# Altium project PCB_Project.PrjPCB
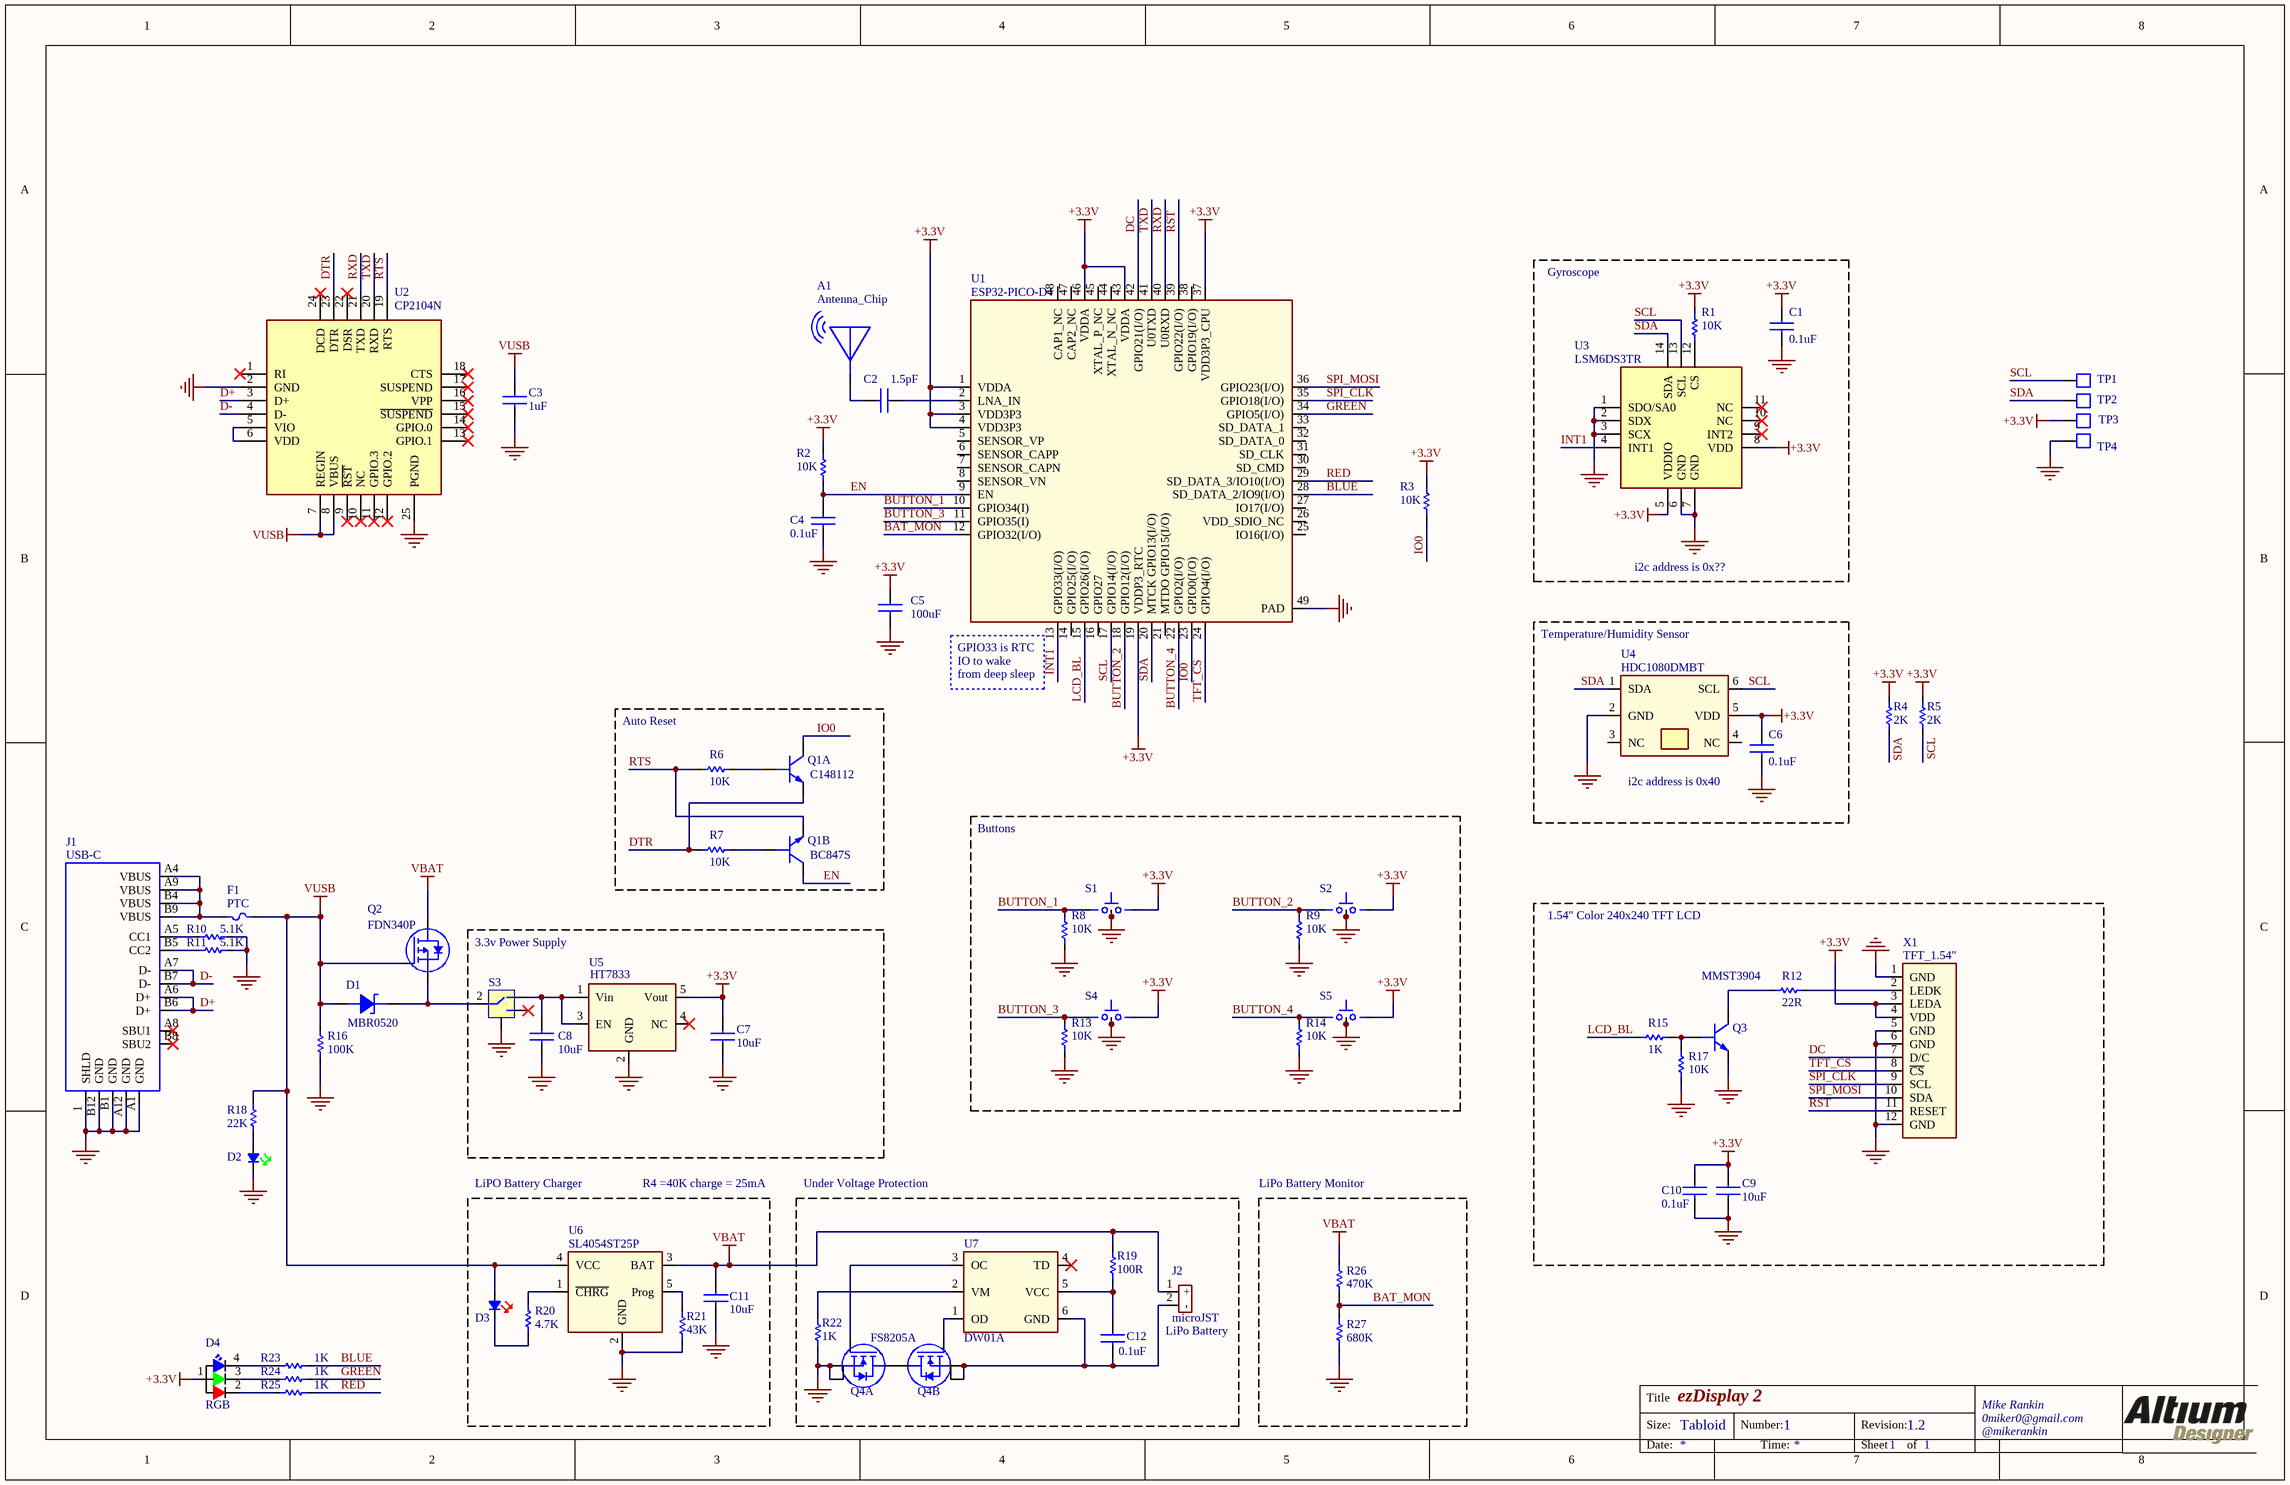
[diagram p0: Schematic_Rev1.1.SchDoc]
1 sheet, 68 parts. Net scope: global (net labels, ports and power ports of the same name join across sheets).
Board file: PCB_Rev1.1.PcbDoc

## Sheet Schematic_Rev1.1.SchDoc: ezDisplay 2
size Tabloid; DrawnBy: x; Engineer: x; Address1: Mike Rankin; Address2: 0miker0@gmail.com; Address3: @mikerankin; DocumentNumber: 1; Revision: 1.2; SheetNumber: 1; SheetTotal: 1

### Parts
A1  Antenna_Chip  [AN9520-245]
C1  0.1uF  [CAPC1005X56N]
C2  1.5pF  [CAPC1005X56N]
C3  1uF  [CAPC1005X56N]
C4  0.1uF  [CAPC1005X56N]
C5  100uF  [CAPC3216X160L]
C6  0.1uF  [CAPC1005X56N]
C7  10uF  [CAPC2012X140N]
C8  10uF  [CAPC2012X140N]
C9  10uF  [CAPC2012X140N]
C10  0.1uF  [CAPC1005X56N]
C11  10uF  [CAPC2012X140N]
C12  0.1uF  [CAPC1005X56N]
D1  MBR0520  [SOD123]
D2  Green Led  [LED1005X40N-Green]  (value not drawn)
D3  Red Led  [LED1005X40N-Red]  (value not drawn)
D4  RGB  [FC-B1010RGBT-HG]
F1  TLC-PSMD050  [PTC2012X70L]  (value not drawn)
J1  USB-C  [TYPE-C-31-M-12]
J2  CON2  [JST_Micro_2PIN]  (value not drawn)  (no BOM)
Q1  Part_Number: C148112  [SOT65P210X110-6N]  (hidden comment: BC847S)  (parts A,B of 2)
Q2  FDN340P  [SOT95P240X110-3N]
Q3  MMST3904  [SC-70]
Q4  FS8205A  [TSOP65P490X110-8N WIDE]  (value not drawn)  (parts A,B of 2)
R1  10K  [RESC1005X40L (0402 FOOTPRINT)]
R2  10K  [RESC1005X40L (0402 FOOTPRINT)]
R3  10K  [RESC1005X40L (0402 FOOTPRINT)]
R4  2K  [RESC1005X40L (0402 FOOTPRINT)]
R5  2K  [RESC1005X40L (0402 FOOTPRINT)]
R6  10K  [RESC1005X40L (0402 FOOTPRINT)]
R7  10K  [RESC1005X40L (0402 FOOTPRINT)]
R8  10K  [RESC1005X40L (0402 FOOTPRINT)]
R9  10K  [RESC1005X40L (0402 FOOTPRINT)]
R10  5.1K  [RESC1005X40L (0402 FOOTPRINT)]
R11  5.1K  [RESC1005X40L (0402 FOOTPRINT)]
R12  22R  [RESC1005X40L (0402 FOOTPRINT)]
R13  10K  [RESC1005X40L (0402 FOOTPRINT)]
R14  10K  [RESC1005X40L (0402 FOOTPRINT)]
R15  1K  [RESC1005X40L (0402 FOOTPRINT)]
R16  100K  [RESC1005X40L (0402 FOOTPRINT)]
R17  10K  [RESC1005X40L (0402 FOOTPRINT)]
R18  22K  [RESC1005X40L (0402 FOOTPRINT)]
R19  100R  [RESC1005X40L (0402 FOOTPRINT)]
R20  4.7K  [RESC1005X40L (0402 FOOTPRINT)]
R21  43K  [RESC1005X40L (0402 FOOTPRINT)]
R22  1K  [RESC1005X40L (0402 FOOTPRINT)]
R23  1K  [RESC1005X40L (0402 FOOTPRINT)]
R24  1K  [RESC1005X40L (0402 FOOTPRINT)]
R25  1K  [RESC1005X40L (0402 FOOTPRINT)]
R26  470K  [RESC1005X40L (0402 FOOTPRINT)]
R27  680K  [RESC1005X40L (0402 FOOTPRINT)]
S1  Push  [122514]  (value not drawn)
S2  Push  [122514]  (value not drawn)
S3  SWITCH SLIDE  [K3-1296S-E1]  (value not drawn)
S4  Push  [122514]  (value not drawn)
S5  Push  [122514]  (value not drawn)
TP1  Test Point, 1mm Top Layer  [TP100TL]  (value not drawn)  (no BOM)
TP2  Test Point, 1mm Top Layer  [TP100TL]  (value not drawn)  (no BOM)
TP3  Test Point, 1mm Top Layer  [TP100TL]  (value not drawn)  (no BOM)
TP4  Test Point, 1mm Top Layer  [TP100TL]  (value not drawn)  (no BOM)
U1  ESP32-PICO-D4  [QFN48_NEWEST 0.5mm pitch]
U2  CP2104N  [24-QFN]
U3  LSM6DS3TR  [LSM6DS3]
U4  HDC1080DMBT  [HDC1080]
U5  HT7833  [SOT95P280X144-5N]
U6  SL4054ST25P  [SOT95P280X144-5N]
U7  DW01A  [SOT95P280X130-6N]
X1  TFT_1.54"  [TFT_GLASS 1.54 INCH]

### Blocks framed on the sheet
Auto Reset: Q1 R6 R7
Buttons: R8 R9 R13 R14 S1 S2 S4 S5
1.54" Color 240x240 TFT LCD: C9 C10 Q3 R12 R15 R17 X1
3.3v Power Supply: C7 C8 S3 U5
LiPo Battery Monitor: R26 R27

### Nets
+3.3V: C1.1 C5.1 C6.1 C7.1 C9.1 C10.1 D4.1 R1.1 R2.1 R3.1 R4.2 R5.2 S1.2(B) S2.2(B) S4.2(B) S5.2(B) TP3.1 U1.1(VDDA) U1.3(VDD3P3) U1.4(VDD3P3) U1.19(VDDP3_RTC) U1.37(VDD3P3_CPU) U1.43(VDDA) U1.46(VDDA) U3.5(VDDIO) U3.8(VDD) U4.5(VDD) U5.5(Vout) X1.3(LEDA) X1.4(VDD)
GND: C1.2 C3.2 C4.2 C5.2 C6.2 C7.2 C8.2 C9.2 C10.2 C11.2 D2.1 J1.1(SHLD) J1.A1(GND) J1.A12(GND) J1.B1(GND) J1.B12(GND) Q3.2(E) Q4.2(S) Q4.3(S) R8.2 R9.2 R10.2 R11.2 R13.2 R14.2 R16.2 R17.2 R21.2 R22.1 R27.2 S1.3 S1.4 S2.3 S2.4 S3.4 S4.3 S4.4 S5.3 S5.4 TP4.1 U1.49(PAD) U2.2(GND) U2.25(PGND) U3.1(SDO/SA0) U3.2(SDX) U3.3(SCX) U3.6(GND) U3.7(GND) U4.2(GND) U5.2(GND) U6.2(GND) X1.1(GND) X1.5(GND) X1.6(GND) X1.12(GND)
VBAT: C11.1 J2.1 Q2.3(D) R19.2 R26.1 U6.3(BAT)
VUSB: C3.1 D1.2(Annode) D3.2 F1.1 Q2.1(G) R16.1 R18.2 U2.7(REGIN) U2.8(VBUS) U6.4(VCC)
BAT_MON: R26.2 R27.1 U1.12(GPIO32(I/O))
BLUE: R23.2 U1.28(SD_DATA_2/IO9(I/O))
BUTTON_1: R8.1 S1.1(A) U1.10(GPIO34(I))
BUTTON_2: R9.1 S2.1(A) U1.18(GPIO12(I/O))
BUTTON_3: R13.1 S4.1(A) U1.11(GPIO35(I))
BUTTON_4: R14.1 S5.1(A) U1.22(GPIO2(I/O))
D+: J1.A6(D+) J1.B6(D+) U2.3(D+)
D-: J1.A7(D-) J1.B7(D-) U2.4(D-)
DC: U1.42(GPIO21(I/O)) X1.7(D/C)
DTR: Q1.1(E1) R7.2 U2.23(DTR)
EN: C4.1 Q1.3(C2) R2.2 U1.9(EN)
GREEN: R24.2 U1.34(GPIO5(I/O))
INT1: U1.13(GPIO33(I/O)) U3.4(INT1)
IO0: Q1.6(C1) R3.2 U1.23(GPIO0(I/O))
LCD_BL: R15.1 U1.15(GPIO26(I/O))
RED: R25.2 U1.29(SD_DATA_3/IO10(I/O))
RST: U1.39(GPIO22(I/O)) X1.11(RESET)
RTS: Q1.4(E2) R6.2 U2.19(RTS)
RXD: U1.40(U0RXD) U2.21(TXD)
SCL: R5.1 TP1.1 U1.17(GPIO14(I/O)) U3.13(SCL) U4.6(SCL)
SDA: R4.1 TP2.1 U1.20(MTCK_GPIO13(I/O)) U3.14(SDA) U4.1(SDA)
SPI_CLK: U1.35(GPIO18(I/O)) X1.9(SCL)
SPI_MOSI: U1.36(GPIO23(I/O)) X1.10(SDA)
TFT_CS: U1.24(GPIO4(I/O)) X1.8(~{CS})
TXD: U1.41(U0TXD) U2.20(RXD)
NetA1_1: A1.1 C2.2
NetC2_1: C2.1 U1.2(LNA_IN)
NetC8_1: C8.1 S3.1 U5.1(Vin) U5.3(EN)
NetC12_1: C12.1 R19.1 U7.5(VCC)
NetC12_2: C12.2 J2.2 Q4.6(S) Q4.7(S) U7.6(GND)
NetD1_1: D1.1(Cathode) Q2.2(S) S3.2
NetD2_2: D2.2 R18.1
NetD3_1: D3.1 R20.1
NetD4_2: D4.2 R25.1
NetD4_3: D4.3 R24.1
NetD4_4: D4.4 R23.1
NetF1_2: F1.2 J1.A4(VBUS) J1.A9(VBUS) J1.B4(VBUS) J1.B9(VBUS)
NetJ1_A5: J1.A5(CC1) R10.1
NetJ1_B5: J1.B5(CC2) R11.1
NetQ1_2: Q1.2(B1) R6.1
NetQ1_5: Q1.5(B2) R7.1
NetQ3_1: Q3.1(B) R15.2 R17.1
NetQ3_3: Q3.3(C) R12.2
NetQ4_1: Q4.1(D) Q4.8(D)
NetQ4_4: Q4.4(G) U7.3(OC)
NetQ4_5: Q4.5(G) U7.1(OD)
NetR1_2: R1.2 U3.12(CS)
NetR12_1: R12.1 X1.2(LEDK)
NetR20_2: R20.2 U6.1(~{CHRG})
NetR21_1: R21.1 U6.5(Prog)
NetR22_2: R22.2 U7.2(VM)
NetU2_5: U2.5(VIO) U2.6(VDD)

Not connected (* = marked no-connect by the designer): J1 A8(SBU1)* B8(SBU2)*; S3 3*; U1 5(SENSOR_VP) 6(SENSOR_CAPP) 7(SENSOR_CAPN) 8(SENSOR_VN) 14(GPIO25(I/O)) 16(GPIO27) 21(MTDO_GPIO15(I/O)) 25(IO16(I/O)) 26(VDD_SDIO_NC) 27(IO17(I/O)) 30(SD_CMD) 31(SD_CLK) 32(SD_DATA_0) 33(SD_DATA_1) 38(GPIO19(I/O)) 44(XTAL_N_NC) 45(XTAL_P_NC) 47(CAP2_NC) 48(CAP1_NC); U2 1(RI)* 9(~{RST})* 10(NC)* 11(GPIO.3)* 12(GPIO.2)* 13(GPIO.1)* 14(GPIO.0)* 15(~{SUSPEND})* 16(VPP)* 17(SUSPEND)* 18(CTS)* 22(DSR)* 24(DCD)*; U3 9(INT2)* 10(NC)* 11(NC)*; U4 3(NC) 4(NC); U5 4(NC)*; U7 4(TD)*

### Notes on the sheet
- Gyroscope
- i2c address is 0x??
- (near U1) GPIO33 is RTC
- (near U1) IO to wake
- (near U1) from deep sleep
- (near U4) Temperature/Humidity Sensor
- i2c address is 0x40
- (near F1) PTC
- LiPO Battery Charger
- R4 =40K charge = 25mA
- Under Voltage Protection
- (near J2) LiPo Battery
- (near J2) microJST

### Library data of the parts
A1 = Antenna_Chip: Antenna Chip 2.4Gig; Manufacturer: Rainsun; Part_Number: C99665; Value: Chip Antenna; Vendor: LCSC
C1 C4 C6 C10 C12 = CAP_0402: CAP 0.1uF 0402; Part_Number: C344190; Manufacturer: CCTC; Vendor: LCSC
C2 = CAP_0402: CAP 1.5pF 0402; Part_Number: C147344; Manufacturer: Dafron; Part_Footprint: 0402; Vendor: LCSC
C3 = CAP_0603: CAP 1uF 16V 0402; Part_Number: C83063; Manufacturer: Walsin; Vendor: LCSC
C5 = CAP_1206: CAP 100uF 6.3V 1206; Part_Number: C87164; Manufacturer: Taiyo Yuden; Vendor: LCSC
C7-C9 = CAP_0805: CAP 10uF 0805; Manufacturer: Samsung; Part_Number: C307520; Vendor: LCSC
C11 = CAP_0805: CAP 10uF 0805; Part_Number: C307520; Manufacturer: Samsung; Vendor: LCSC
D1 = MBR0520-TP: DIODE SCHOTTKY 20V 500MA SOD123; Manufacturer: CJ; Part_Number: C475717; Vendor: LCSC
D2 = LED_0402_SMALL_GREEN: LED Green 0402; Part_Number: C74338; Manufacturer: Lite-On; Part_Footprint: 0402; Vendor: LCSC
D3 = LED_0402_SMALL_Red: LED RED 0402; Part_Number: C364556; Manufacturer: Lite-On; Part_Footprint: 0402; Vendor: LCSC
D4 = FC-B1010RGBT-HG: LED,RGB LED,SMD,RoHS; Part_Number: C158099; Manufacturer: Foshan; Vendor: LCSC; Value: RGB Led
F1 = PTC_FUSE: PTC FUSE 500mA hold, 1A trip 0805 SMD; Manufacturer: TLC; Part_Number: C261942; Vendor: LCSC
J1 = USB-C: CONN RECPT USB-C; Manufacturer: KHE; Part_Number: C165948; Part_Footprint: SMT; Vendor: LCSC
J2 = JST_Micro_CONN_2PIN: JST MIcro CONN 2POS
Q1 = BC847S: TRANS 2NPN 44V 0.1A SC-70-6; Manufacturer: Changjiang; Vendor: LCSC
Q2 = FDN340P: MOSFET P-CH 20V 2A SOT-23; Manufacturer: On Semi; Part_Number: C75469; Vendor: LCSC
Q3 = MMST3904: TRANSISTOR NPN GP 40V SC-70; Manufacturer: Changjiang; Part_Number: C54879; Vendor: LCSC
Q4 = FS8205A: MOSFET 2N-CH 20V 6A TSSOP-8L; Manufacturer: Fortune; Part_Number: C16052; Vendor: LCSC
R1-R3 R6 R7 R17 = RES_0402: RES 10K 0402; Part_Number: C258091; Manufacturer: Guangdong; Vendor: LCSC
R4 R5 = RES_0402: RES 2K 0402; Manufacturer: LIZ Elec; Part_Number: C100291; Vendor: LCSC
R8 R9 R13 R14 = RES_0402: RES 10K 0402; Part_Number: C258091; Manufacturer: Guangdong; Part_Footprint: 0402; Vendor: LCSC
R10 R11 = RES_0603: RES 5.1K 0402; Manufacturer: TyoHM; Part_Number: C325521; Vendor: LCSC
R12 = RES_0402: RES 22R 0402; Part_Number: C25092; Manufacturer: Uniroyal; Vendor: LCSC
R15 R22-R25 = RES_0402: RES 1K 0402; Part_Number: C106235; Manufacturer: Yageo; Vendor: LCSC
R16 = RES_0603: RES 100K 0402; Manufacturer: Uniroyal Elec; Part_Number: C25741; Vendor: LCSC
R18 = RES_0603: RES 22K 0402; Manufacturer: LIZ Elec; Part_Number: C100310; Vendor: LCSC
R19 = RES_0603: RES 100R 0402; Manufacturer: Yageo; Part_Number: C106232; Vendor: LCSC
R20 = RES_0603: RES 4.7K 0402; Manufacturer: LIZ Elec; Part_Number: C100139; Vendor: LCSC
R21 = RES_0603: RES 43K 0402; Manufacturer: Uniroyal; Part_Number: C8329; Vendor: LCSC
R26 = RES_0402: RES 470K 0402; Vendor: LCSC
R27 = RES_0402: RES 680K 0402; Vendor: LCSC
S1 S2 S4 S5 = Side Actuated Button R/A: Part_Number: C319377; Manufacturer: HYP; Vendor: LCSC
S3 = K3-1296S-E1: SWITCH SLIDE SMD; Manufacturer: Korean Hroparts Elec; Part_Number: C128955; Vendor: LCSC
U1 = ESP32-PICO-D4: RF Transceiver ICs QFN-48_7x7x05P RoHS; Manufacturer: Espressif; Part_Number: C193707; Part_Footprint: QFN-48; Vendor: LCSC
U2 = CP2104N: IC BRIDGE USB TO UART 24QFN; Manufacturer: Silicon Labs; Part_Number: C47742; Vendor: LCSC
U3 = LSM6DS3 (obsolete): IMU ACCEL/GYRO I2C/SPI 14VFLGA; Manufacturer: ST MICRO; Part_Number: C95230; Vendor: LCSC
U4 = HDC1080DMBT: Humidity/Temperature Sensor; Manufacturer: Texas Instruments; Part_Number: C82227; Vendor: LCSC
U5 = HT7833: IC LDO 3.3V 0.5A SOT23-5; Manufacturer: Holtek; Part_Number: C164106; Part_Footprint: SOT-23-5L; Vendor: LCSC
U6 = SL4054ST25P: Charger IC Lithium-Ion/Polymer SOT23-5; Manufacturer: Techfuse; Part_Number: C258510; Part_Footprint: SOT-23-5L; Vendor: LCSC
U7 = DW01A: IC LITHIUM BATT PROTECT SOT-23-6L; Manufacturer: PUOLOP; Part_Number: C351410; Vendor: LCSC
X1 = TFT_GLASS 1.54 INCH COLOR: 1.54 INCH TFT GLASS COLOR; Part_Number: ER-TFT1.54-1; Manufacturer: BuyDisplay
